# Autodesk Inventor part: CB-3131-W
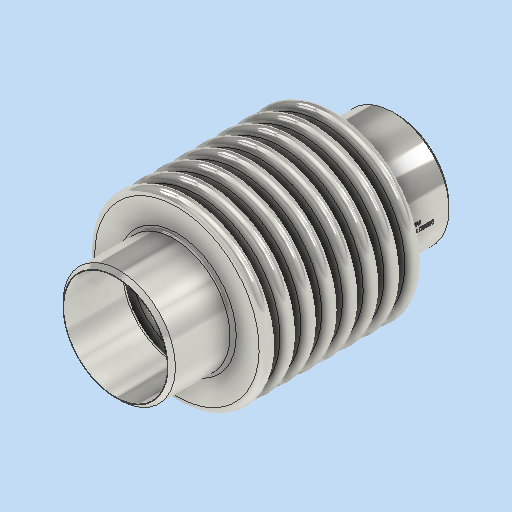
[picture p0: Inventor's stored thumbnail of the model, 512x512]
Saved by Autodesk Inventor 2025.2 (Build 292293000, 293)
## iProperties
Company: DN.RU
Created: 2026-04
Part Number: CB-3131-W
Material: Типовые
Document SubType Name: Modeling
Designer: DN.RU
Density: 6.01902 g/cm^3
Appearance: По умолчанию
Description: D140-02124
Mass: 2500 g
Surface Area: 5925.31 cm^2
Volume: 415.35 cm^3
Author: DN.RU
Title: Компенсатор сильфонный осевой DN.ru Ду100 Ру16
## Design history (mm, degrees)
sketch "Эскиз1"
  geometry: L1 (0, 0)-(0, -135); L2 (54, -135)-(54, 0); L3 (54, 0)-(0, 0); L4 (54, 0)-(54, -10); L5 (29, -10)-(79, -10); L6 (29, -16)-(79, -16); L7 (79, -4)-(29, -4); L8 (79, -15)-(29, -15); L9 (29, -5)-(79, -5); L10 (79, -24)-(29, -24); L11 (29, -25)-(79, -25); L12 (29, -30)-(79, -30); L13 (29, -36)-(79, -36); L14 (79, -35)-(29, -35); L15 (79, -44)-(29, -44); L16 (29, -45)-(79, -45); L17 (29, -50)-(79, -50); L18 (29, -56)-(79, -56); L19 (79, -55)-(29, -55); L20 (79, -64)-(29, -64); L21 (29, -65)-(79, -65); L22 (29, -70)-(79, -70); L23 (29, -76)-(79, -76); L24 (79, -75)-(29, -75); L25 (0, -135)-(54, -135); L26 (54, -135)-(50, -135); L27 (54, -64)-(53, -64); L28 (50, -135)-(50, -75); L29 (54, -65)-(53, -65); L30 (53, -65)-(53, -55); L31 (54, -45)-(53, -45); L32 (53, -45)-(53, -35); L33 (54, -25)-(53, -25); L34 (53, -25)-(53, -15); L35 (54, -5)-(53, -5); L36 (53, -5)-(53, 0); A1 r 6 centre (29, -10) between (29, -4) and (29, -16); A2 r 6 centre (79, -10) between (79, -16) and (79, -4); A3 r 5 centre (29, -10) between (29, -5) and (29, -15); A4 r 5 centre (79, -10) between (79, -15) and (79, -5); A5 r 5 centre (29, -30) between (29, -25) and (29, -35); A6 r 6 centre (29, -30) between (29, -24) and (29, -36); A7 r 5 centre (79, -30) between (79, -35) and (79, -25); A8 r 6 centre (79, -30) between (79, -36) and (79, -24); A9 r 5 centre (29, -50) between (29, -45) and (29, -55); A10 r 6 centre (29, -50) between (29, -44) and (29, -56); A11 r 5 centre (79, -50) between (79, -55) and (79, -45); A12 r 6 centre (79, -50) between (79, -56) and (79, -44); A13 r 5 centre (29, -70) between (29, -65) and (29, -75); A14 r 6 centre (29, -70) between (29, -64) and (29, -76); A15 r 5 centre (79, -70) between (79, -75) and (79, -65); A16 r 6 centre (79, -70) between (79, -76) and (79, -64); 18 further points
  constraints: 80 end point, 32 point on circle, 16 centre point, 15 point on line, 6 midpoint, 5 perpendicular, 4 tangent, 3 parallel, 2 vertical, 1 horizontal, 69 other
  dimensions: "d0" = 135 distance of L1.start L1.end; "d1" = 54 distance of L2.start L1.end; "d3" = 10 distance of L2.end L4.end; "d4" = 25 distance of L4.end L5.end; "d5" = 12 diameter of A2; "d6" = 1 distance between parallel lines of L6 L8; "d9" = 20 distance of L4.end point (54, -30); "d14" = 4 distance of L2.start L26.end; "d15" = 1 distance of L27.start L27.end; "d16" = 1 distance of L29.start L29.end; "d17" = 1 distance of L31.start L31.end; "d18" = 1 distance of L33.start L33.end; "d19" = 1 distance of L35.start L35.end
revolve "Вращение1" sketch "Эскиз1" stored, may be unused: angle "d20" = 360 deg
mirror "Зеркальное отражение1"
chamfer "Фаска1" distance "d21" = 3.5; stored, may be unused: second distance "d22" = 2, angle "d23" = 45 deg
fillet "Сопряжение1" dims "d24" = 3
node "РабПлоскость1"
sketch "Эскиз2"
  geometry: L1 (4.893, 15.322)-(4.893, -12.74); L2 (4.893, -12.74)-(-3.237, -12.74); L3 (-3.237, -12.74)-(-3.237, 15.322); L4 (-3.237, 15.322)-(4.893, 15.322); 1 further point
  constraints: 2 other
feature "Рельеф1" sketch "Эскиз2" dims "d25" = 0.1, "d26" = 0
node "Твердое тело1"
node "Эскиз — прямоугольный массив1" dims "d9" = 20, "d12" = 10
